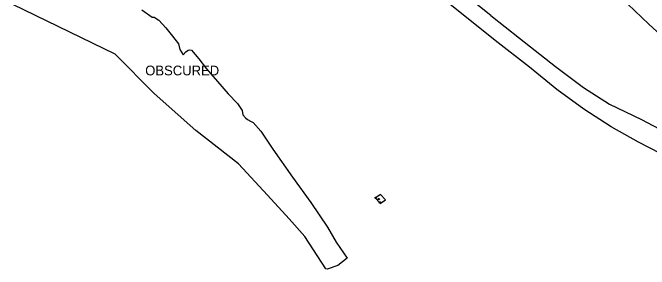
# Model space of a CAD drawing. Extents: x 368532 to 392481, y 10654822 to 10676899.
# Drawn here: x 380420.1 to 380746.2, y 10658302.7 to 10658434.2 of the extents above; entities that cross this region are included whole.
import ezdxf

# ---------------------------------------------------------------- set-up
doc = ezdxf.new("R2010")
doc.units = 0
for name, color, linetype in [('p_dtm obscured area', 7, 'Continuous'), ('p_dtm slab', 7, 'Continuous'), ('p_road dirt road', 7, 'Continuous'), ('p_structure unidentified', 7, 'Continuous')]:
    doc.layers.add(name, color=color, linetype=linetype)

msp = doc.modelspace()

# ---------------------------------------------------------------- linework, layer by layer
at = {"layer": 'p_dtm obscured area'}
msp.add_lwpolyline([(380486.26, 10658435.79), (380491.48, 10658431.91), (380492.55, 10658431.9), (380495.05, 10658430.44), (380498.49, 10658426.5), (380502.02, 10658422.28), (380505.12, 10658418.34), (380505.78, 10658415.34), (380507.47, 10658412.61), (380508.72, 10658414.2), (380510.01, 10658415.06), (380510.79, 10658415.25), (380511.74, 10658415.05), (380515.5, 10658410.53), (380519.33, 10658405.48), (380524.95, 10658398.99), (380530.55, 10658392.56), (380535.27, 10658387.62), (380537.72, 10658384.04), (380538.03, 10658381.79), (380539.42, 10658380.29), (380540.47, 10658379.52), (380541.86, 10658378.59), (380543.28, 10658377.98), (380547.15, 10658373.58), (380553.29, 10658364.19), (380563.46, 10658349.98), (380572.76, 10658336.98), (380581.35, 10658324.32), (380585.87, 10658316.53), (380591.44, 10658308.37), (380586.66, 10658304.67), (380581.25, 10658302.68), (380580.47, 10658302.88), (380569.7, 10658319.48), (380561.76, 10658328.62), (380550.71, 10658340.74), (380535.81, 10658356.7), (380513.92, 10658373.84), (380492.6, 10658392.76), (380472.57, 10658412.94), (380420.12, 10658438.47)], dxfattribs=at)
at = {"layer": 'p_dtm slab'}
for p, q in [((380606.18, 10658339.01), (380607.85, 10658337.02)), ((380608.57, 10658341.06), (380606.35, 10658339.5)), ((380608.37, 10658336.39), (380611.18, 10658338.33)), ((380611.18, 10658338.33), (380608.57, 10658341.06)), ((380608.23, 10658336.56), (380608.37, 10658336.39))]:
    msp.add_line(p, q, dxfattribs=at)
at = {"layer": 'p_road dirt road'}
for p, q in [((380650.04, 10658433.88), (380634.11, 10658446.86)), ((380665, 10658432.87), (380647.58, 10658446.78)), ((380746.05, 10658428.36), (380731.27, 10658442.51)), ((380667.27, 10658420.04), (380650.04, 10658433.88)), ((380665, 10658432.87), (380679.77, 10658421.2)), ((380761.07, 10658414.43), (380746.05, 10658428.36)), ((380684.94, 10658406.36), (380667.27, 10658420.04)), ((380679.77, 10658421.2), (380698.2, 10658406.64)), ((380698.2, 10658406.64), (380712.62, 10658395.81)), ((380698.89, 10658394.9), (380684.94, 10658406.36)), ((380712.69, 10658384.73), (380698.89, 10658394.9)), ((380712.62, 10658395.81), (380725.85, 10658387.29)), ((380725.85, 10658387.29), (380742.19, 10658379.43)), ((380726.78, 10658375.71), (380712.69, 10658384.73)), ((380742.19, 10658379.43), (380755.1, 10658372.7)), ((380740.78, 10658367.8), (380726.78, 10658375.71)), ((380752.05, 10658362.08), (380740.78, 10658367.8))]:
    msp.add_line(p, q, dxfattribs=at)
at = {"layer": 'p_structure unidentified'}
for centre in [(380606.01, 10658339.34), (380607.61, 10658338.68), (380608.22, 10658336.93)]:
    msp.add_circle(centre, 0.375, dxfattribs=at)

# ---------------------------------------------------------------- texts
at = {"layer": 'p_dtm obscured area'}
msp.add_text(' OBSCURED', height=5, dxfattribs=at).set_placement((380486.14, 10658402.1))

doc.saveas('drawing.dxf')
